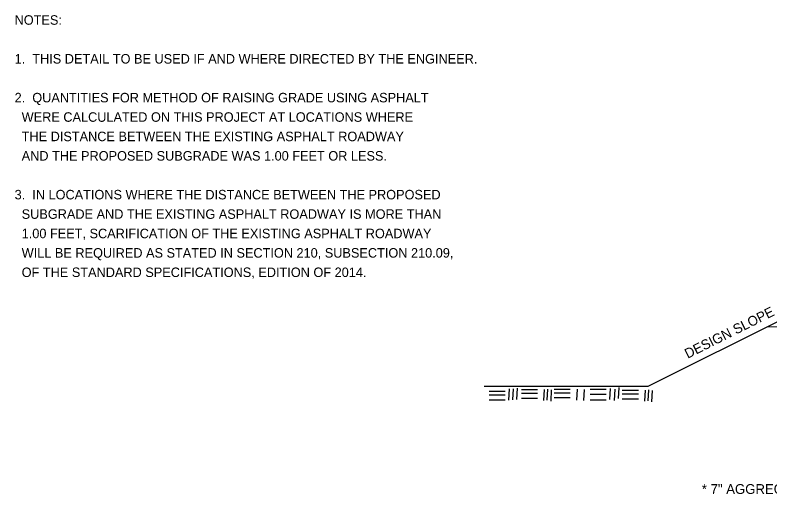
# Model space of a CAD drawing. Extents: x 634177 to 635904, y 289936 to 290970.
# Drawn here: x 635628.85 to 635674.89, y 290597.46 to 290626.86 of the extents above; entities that cross this region are included whole.
import ezdxf

# ---------------------------------------------------------------- set-up
doc = ezdxf.new("R2010")
doc.units = 0
doc.layers.add('1', color=7, linetype='Continuous')
doc.layers.add('R_Draft', color=7, linetype='Continuous')

msp = doc.modelspace()

# ---------------------------------------------------------------- linework, layer by layer
at = {"layer": 'R_Draft'}
for p, q in [((635667.465, 290604.212), (635679.883, 290610.417)), ((635674.699, 290607.826), (635699.814, 290608.826)), ((635657.456, 290604.212), (635667.465, 290604.212)), ((635658.995, 290604.045), (635658.955, 290603.368)), ((635659.226, 290604.061), (635659.19, 290603.381)), ((635659.487, 290604.085), (635659.445, 290603.41)), ((635659.733, 290604.01), (635660.712, 290604.01)), ((635661.125, 290604.01), (635661.089, 290603.333)), ((635661.329, 290604.032), (635661.29, 290603.359)), ((635661.561, 290603.988), (635661.524, 290603.308)), ((635661.737, 290604.04), (635662.717, 290604.04)), ((635663.13, 290604.04), (635663.092, 290603.363)), ((635663.564, 290604.014), (635663.528, 290603.339)), ((635663.93, 290604.023), (635664.909, 290604.023)), ((635665.152, 290604.08), (635665.111, 290603.403)), ((635665.441, 290604.022), (635665.402, 290603.348)), ((635665.671, 290604.141), (635665.631, 290603.46)), ((635665.89, 290603.967), (635666.871, 290603.967)), ((635667.282, 290603.967), (635667.248, 290603.29)), ((635667.487, 290603.99), (635667.45, 290603.311)), ((635657.759, 290603.909), (635658.736, 290603.909)), ((635657.759, 290603.684), (635658.736, 290603.684)), ((635659.733, 290603.786), (635660.712, 290603.786)), ((635661.737, 290603.814), (635662.717, 290603.814)), ((635661.737, 290603.513), (635662.717, 290603.513)), ((635663.93, 290603.735), (635664.909, 290603.735)), ((635665.89, 290603.741), (635666.871, 290603.741)), ((635667.719, 290603.941), (635667.679, 290603.266)), ((635657.759, 290603.379), (635658.736, 290603.379)), ((635659.733, 290603.484), (635660.712, 290603.484)), ((635663.93, 290603.386), (635664.909, 290603.386)), ((635665.89, 290603.439), (635666.871, 290603.439))]:
    msp.add_line(p, q, dxfattribs=at)

# ---------------------------------------------------------------- texts
at = {"layer": '1'}
for s, p in [('NOTES:', (635628.822, 290626.267)), ('1.  THIS DETAIL TO BE USED IF AND WHERE DIRECTED BY THE ENGINEER.', (635628.822, 290623.899)), ('2.  QUANTITIES FOR METHOD OF RAISING GRADE USING ASPHALT', (635628.822, 290621.53)), ('  WERE CALCULATED ON THIS PROJECT AT LOCATIONS WHERE', (635628.822, 290620.346)), ('  THE DISTANCE BETWEEN THE EXISTING ASPHALT ROADWAY', (635628.822, 290619.162)), ('  AND THE PROPOSED SUBGRADE WAS 1.00 FEET OR LESS.', (635628.822, 290617.978)), ('3.  IN LOCATIONS WHERE THE DISTANCE BETWEEN THE PROPOSED', (635628.822, 290615.61)), ('  SUBGRADE AND THE EXISTING ASPHALT ROADWAY IS MORE THAN', (635628.822, 290614.425)), ('  1.00 FEET, SCARIFICATION OF THE EXISTING ASPHALT ROADWAY', (635628.822, 290613.241)), ('  WILL BE REQUIRED AS STATED IN SECTION 210, SUBSECTION 210.09,', (635628.822, 290612.057)), ('  OF THE STANDARD SPECIFICATIONS, EDITION OF 2014.', (635628.822, 290610.873))]:
    msp.add_text(s, height=0.58, dxfattribs=at).set_placement(p)
at = {"layer": 'R_Draft'}
msp.add_text('DESIGN SLOPE', height=0.6, rotation=26.565, dxfattribs=at).set_placement((635669.876, 290605.883))
msp.add_text('* 7" AGGREGATE BASE COURSE (CLASS 7)', height=0.6, dxfattribs=at).set_placement((635670.739, 290597.638))

doc.saveas('drawing.dxf')
